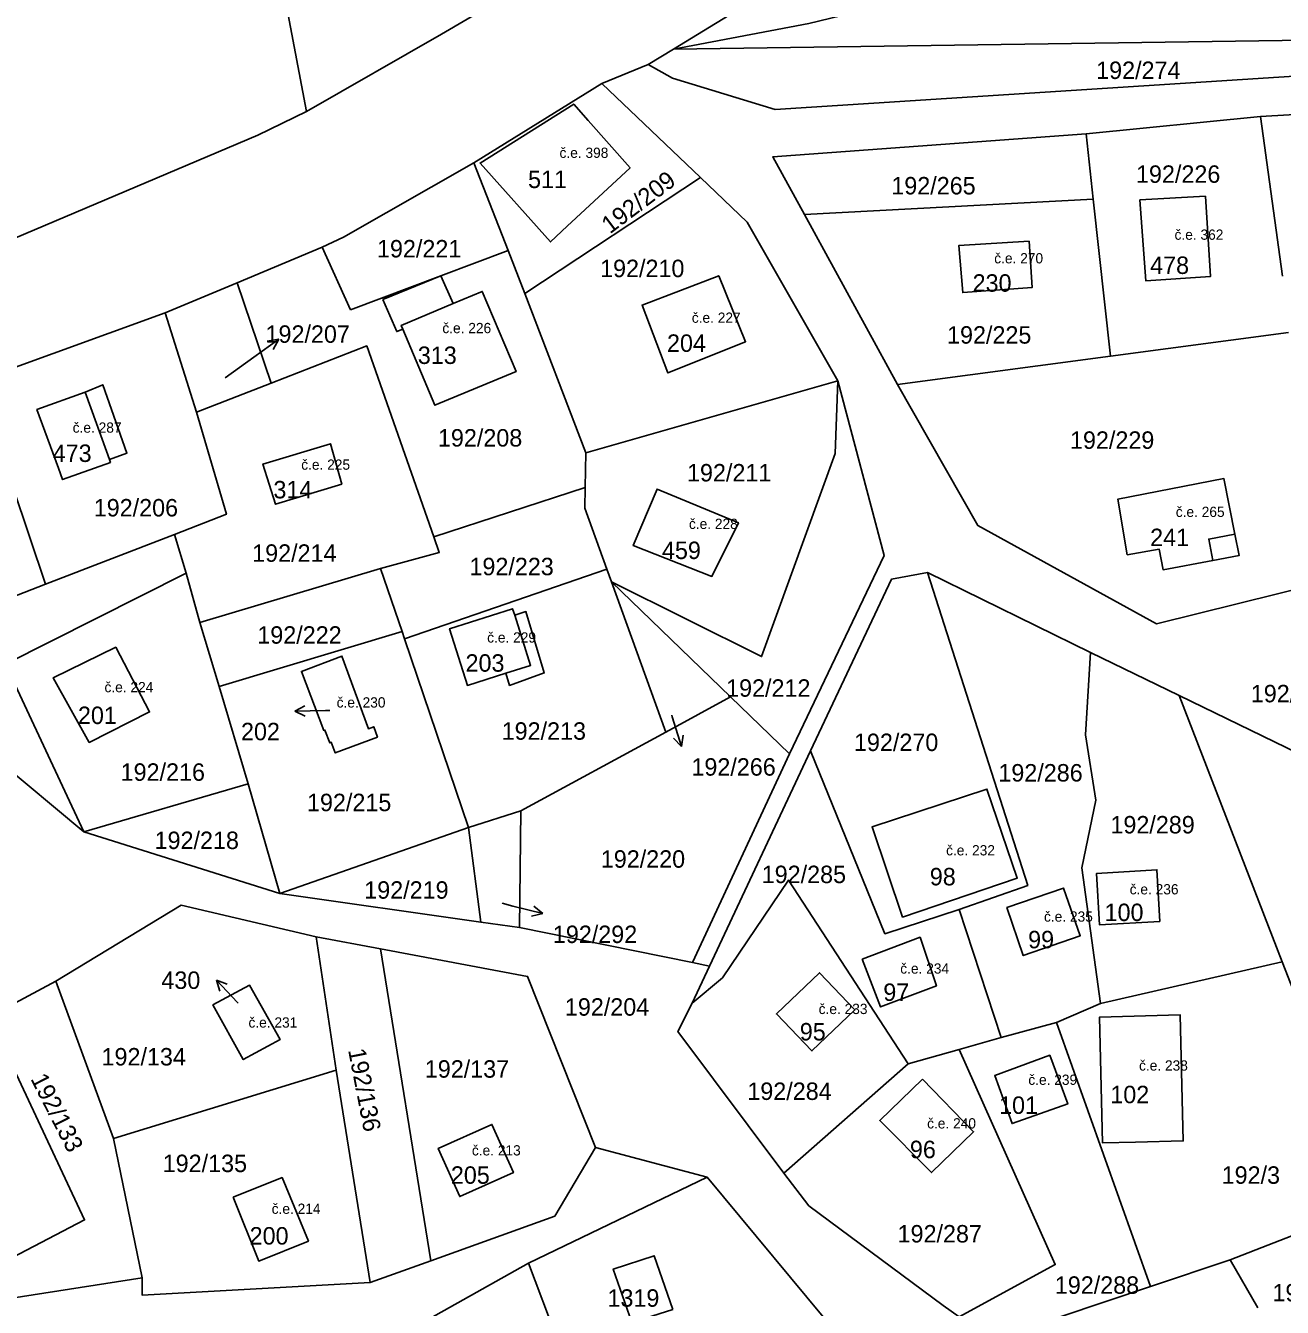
# Model space of a CAD drawing. Extents: x -887272 to -877616, y -1026687 to -1019819.
# Drawn here: x -882201.9 to -882079.4, y -1024136.8 to -1024011.9 of the extents above; entities that cross this region are included whole.
import ezdxf

# ---------------------------------------------------------------- set-up
doc = ezdxf.new("R2010")
doc.units = 0
for name, color, linetype in [('Definiční body', 7, 'Continuous'), ('Hranice parcel', 7, 'Continuous'), ('Parcelní čísla', 7, 'Continuous'), ('Polygon budovy', 7, 'Continuous'), ('Pop  PČ popisy', 7, 'Continuous'), ('Vnitřní kresba', 7, 'Continuous')]:
    doc.layers.add(name, color=color, linetype=linetype)

msp = doc.modelspace()

# ---------------------------------------------------------------- linework, layer by layer
at = {"layer": 'Hranice parcel'}
for p, q in [((-882138.72, -1024014.17), (-882123.98, -1024005.14)), ((-882141.19, -1024015.69), (-882138.72, -1024014.17)), ((-882145.71, -1024017.54), (-882141.19, -1024015.69)), ((-882145.71, -1024017.54), (-882158.18, -1024025.27)), ((-882136.1, -1024026.69), (-882145.71, -1024017.54)), ((-882081.54, -1024020.75), (-882098.51, -1024022.43)), ((-882079.39, -1024036.31), (-882081.54, -1024020.75)), ((-882098.51, -1024022.43), (-882097.82, -1024028.81)), ((-882158.18, -1024025.27), (-882154.84, -1024033.81)), ((-882153.2, -1024037.99), (-882136.1, -1024026.69)), ((-882097.82, -1024028.81), (-882125.97, -1024030.31)), ((-882096.15, -1024044.11), (-882097.82, -1024028.81)), ((-882125.97, -1024030.31), (-882116.91, -1024046.86)), ((-882172.96, -1024033.47), (-882181.25, -1024036.95)), ((-882170.21, -1024039.58), (-882172.96, -1024033.47)), ((-882153.2, -1024037.99), (-882154.84, -1024033.81)), ((-882181.25, -1024036.95), (-882188.26, -1024039.89)), ((-882177.94, -1024046.73), (-882181.25, -1024036.95)), ((-882147.26, -1024053.51), (-882153.2, -1024037.99)), ((-882206.58, -1024046.52), (-882188.26, -1024039.89)), ((-882188.26, -1024039.89), (-882185.22, -1024049.56)), ((-882096.15, -1024044.11), (-882078.8, -1024041.81)), ((-882116.91, -1024046.86), (-882096.15, -1024044.11)), ((-882199.93, -1024066.33), (-882206.58, -1024046.52)), ((-882185.22, -1024049.56), (-882177.94, -1024046.73)), ((-882147.26, -1024053.51), (-882122.72, -1024046.51)), ((-882147.32, -1024056.9), (-882147.26, -1024053.51)), ((-882162.09, -1024061.72), (-882147.32, -1024056.9)), ((-882187.35, -1024061.47), (-882199.93, -1024066.33)), ((-882186.22, -1024065.24), (-882187.35, -1024061.47)), ((-882167.27, -1024064.79), (-882184.87, -1024070.04)), ((-882165.18, -1024070.94), (-882167.27, -1024064.79)), ((-882145.21, -1024064.85), (-882164.94, -1024071.65)), ((-882145.21, -1024064.85), (-882144.76, -1024066.09)), ((-882199.93, -1024066.33), (-882217.07, -1024073.03)), ((-882184.87, -1024070.04), (-882186.22, -1024065.24)), ((-882144.76, -1024066.09), (-882133.16, -1024077.29)), ((-882139.48, -1024080.73), (-882144.76, -1024066.09)), ((-882098.08, -1024072.99), (-882113.98, -1024065.19)), ((-882183, -1024076.28), (-882184.87, -1024070.04)), ((-882165.18, -1024070.94), (-882183, -1024076.28)), ((-882164.94, -1024071.65), (-882165.18, -1024070.94)), ((-882164.94, -1024071.65), (-882158.69, -1024090.04)), ((-882196.2, -1024090.44), (-882217.07, -1024073.03)), ((-882089.45, -1024077.18), (-882098.08, -1024072.99)), ((-882183, -1024076.28), (-882180.16, -1024085.79)), ((-882133.16, -1024077.29), (-882139.48, -1024080.73)), ((-882133.16, -1024077.29), (-882127.41, -1024082.85)), ((-882089.45, -1024077.18), (-882079.4, -1024103.11)), ((-882153.6, -1024088.41), (-882139.48, -1024080.73)), ((-882125.39, -1024082.57), (-882135.22, -1024103.54)), ((-882136.89, -1024103.2), (-882127.41, -1024082.85)), ((-882196.2, -1024090.44), (-882180.16, -1024085.79)), ((-882180.16, -1024085.79), (-882177.1, -1024096.46)), ((-882158.69, -1024090.04), (-882153.6, -1024088.41)), ((-882153.6, -1024088.41), (-882153.74, -1024099.78)), ((-882177.1, -1024096.46), (-882158.69, -1024090.04)), ((-882157.5, -1024099.25), (-882158.69, -1024090.04)), ((-882177.1, -1024096.46), (-882196.2, -1024090.44)), ((-882157.5, -1024099.25), (-882177.1, -1024096.46)), ((-882106.8, -1024110.48), (-882110.89, -1024098.01)), ((-882153.74, -1024099.78), (-882157.5, -1024099.25)), ((-882136.89, -1024103.2), (-882153.74, -1024099.78)), ((-882171.6, -1024113.68), (-882173.55, -1024100.7)), ((-882167.27, -1024101.87), (-882173.55, -1024100.7)), ((-882162.36, -1024132.25), (-882167.27, -1024101.87)), ((-882136.92, -1024107.16), (-882135.22, -1024103.54)), ((-882135.22, -1024103.54), (-882136.89, -1024103.2)), ((-882079.4, -1024103.11), (-882097.11, -1024107.19)), ((-882076.7, -1024110.12), (-882079.4, -1024103.11)), ((-882205.42, -1024108.48), (-882198.92, -1024105.01)), ((-882198.92, -1024105.01), (-882193.28, -1024120.35)), ((-882097.11, -1024107.19), (-882101.42, -1024109.04)), ((-882106.8, -1024110.48), (-882101.42, -1024109.04)), ((-882101.42, -1024109.04), (-882092.24, -1024134.77)), ((-882110.9, -1024111.66), (-882106.8, -1024110.48)), ((-882115.87, -1024113.05), (-882110.9, -1024111.66)), ((-882193.28, -1024120.35), (-882171.6, -1024113.68)), ((-882168.3, -1024134.38), (-882171.6, -1024113.68)), ((-882127.99, -1024123.73), (-882115.87, -1024113.05)), ((-882114.47, -1024114.55), (-882118.63, -1024118.59)), ((-882193.28, -1024120.35), (-882190.49, -1024133.91)), ((-882135.46, -1024124.1), (-882146.33, -1024121.21)), ((-882125.54, -1024126.91), (-882127.99, -1024123.73)), ((-882152.85, -1024132.47), (-882135.46, -1024124.1)), ((-882121.99, -1024140.29), (-882135.46, -1024124.1)), ((-882084.49, -1024132.15), (-882072.69, -1024127.57)), ((-882168.3, -1024134.38), (-882162.36, -1024132.25)), ((-882147.02, -1024148.04), (-882152.85, -1024132.47)), ((-882092.24, -1024134.77), (-882084.49, -1024132.15)), ((-882084.49, -1024132.15), (-882081.79, -1024136.83)), ((-882190.49, -1024133.91), (-882208.64, -1024136.73)), ((-882092.24, -1024134.77), (-882105.5, -1024139.21))]:
    msp.add_line(p, q, dxfattribs=at)
for points in [[(-882174.49, -1024020.26), (-882208.33, -1023841.98), (-882227.5, -1023772.45), (-882213.17, -1023769.2), (-882180.99, -1023853.37), (-882162.93, -1023941.67)], [(-882138.72, -1024014.17), (-882125.55, -1024011.67), (-882085.96, -1024002.08), (-882063.17, -1024001.87), (-882034.49, -1024011.62), (-882004.55, -1024020.66), (-881996.26, -1024020.9)], [(-882148.29, -1024005.05), (-882161.34, -1024012.72), (-882174.49, -1024020.26)], [(-881966.06, -1024029.4), (-882045.19, -1024012.84), (-882138.72, -1024014.17)], [(-881990.45, -1024031.46), (-882004.32, -1024026.5), (-882043.3, -1024015.89), (-882047.34, -1024014.83), (-882128.82, -1024020.06), (-882138.81, -1024017.01), (-882141.19, -1024015.69)], [(-882147.04, -1024021.13), (-882148.45, -1024019.53), (-882157.57, -1024025.28), (-882150.72, -1024032.97)], [(-882057.94, -1024032.5), (-882065.31, -1024019.82), (-882081.54, -1024020.75)], [(-882340.1, -1024040.68), (-882291.8, -1024041.02), (-882266.44, -1024041.52), (-882231.92, -1024039.84), (-882208.92, -1024035.12), (-882179.22, -1024022.58), (-882174.49, -1024020.26)], [(-882150.72, -1024032.97), (-882149.08, -1024031.43), (-882142.96, -1024025.76), (-882147.04, -1024021.13)], [(-882098.51, -1024022.43), (-882129.05, -1024024.69), (-882125.97, -1024030.31)], [(-882158.18, -1024025.27), (-882170.87, -1024032.49), (-882172.96, -1024033.47)], [(-882122.72, -1024046.51), (-882131.54, -1024031.03), (-882136.1, -1024026.69)], [(-882086.4, -1024036.35), (-882086.89, -1024028.52), (-882093.28, -1024028.88), (-882092.71, -1024036.76), (-882086.4, -1024036.35)], [(-882154.84, -1024033.81), (-882161.39, -1024036.27), (-882170.21, -1024039.58)], [(-882103.78, -1024037.42), (-882104.08, -1024032.9), (-882110.92, -1024033.31), (-882110.54, -1024037.9), (-882103.78, -1024037.42)], [(-882160.2, -1024038.98), (-882161.39, -1024036.27), (-882167.05, -1024038.59)], [(-882141.79, -1024039.12), (-882139.27, -1024045.73), (-882131.7, -1024042.7), (-882134.31, -1024036.26), (-882141.79, -1024039.12)], [(-882167.05, -1024038.59), (-882165.7, -1024041.71), (-882165.11, -1024041.46), (-882161.99, -1024048.88), (-882154.07, -1024045.61), (-882157.36, -1024037.79), (-882160.2, -1024038.98)], [(-882177.94, -1024046.73), (-882168.62, -1024043.1), (-882162.09, -1024061.72)], [(-882198.66, -1024055), (-882198.26, -1024056.13), (-882193.59, -1024054.46), (-882193.69, -1024054.18), (-882191.99, -1024053.54), (-882194.34, -1024046.88), (-882196.04, -1024047.62), (-882200.75, -1024049.31), (-882198.66, -1024055)], [(-882144.76, -1024066.09), (-882130.14, -1024073.37), (-882122.96, -1024053.6), (-882122.72, -1024046.51)], [(-882127.41, -1024082.85), (-882118.21, -1024063.51), (-882122.72, -1024046.51)], [(-882116.91, -1024046.86), (-882109.08, -1024060.61), (-882091.67, -1024070.17), (-882075.8, -1024066.27)], [(-882187.35, -1024061.47), (-882182.29, -1024059.51), (-882185.22, -1024049.56)], [(-882172.16, -1024052.64), (-882178.74, -1024054.62), (-882177.51, -1024058.53), (-882171.05, -1024056.59), (-882172.16, -1024052.64)], [(-882091.02, -1024064.92), (-882086.18, -1024064.01), (-882083.62, -1024063.53), (-882084.03, -1024061.44), (-882085.09, -1024056.03), (-882095.44, -1024058.05), (-882094.51, -1024063.45), (-882091.4, -1024062.91), (-882091.02, -1024064.92)], [(-882147.32, -1024056.9), (-882147.35, -1024058.92), (-882145.21, -1024064.85)], [(-882132.4, -1024060.34), (-882140.32, -1024057.06), (-882142.64, -1024062.56), (-882134.98, -1024065.56), (-882132.4, -1024060.34)], [(-882162.09, -1024061.72), (-882161.56, -1024063.23), (-882167.27, -1024064.79)], [(-882186.22, -1024065.24), (-882203.83, -1024074.1), (-882196.2, -1024090.44)], [(-882113.98, -1024065.19), (-882117.47, -1024065.82), (-882125.39, -1024082.57)], [(-882110.89, -1024098.01), (-882104.21, -1024095.67), (-882113.98, -1024065.19)], [(-882154.4, -1024068.72), (-882160.55, -1024070.67), (-882158.8, -1024076.18), (-882155.08, -1024075), (-882154.7, -1024076.19), (-882151.32, -1024074.97), (-882153.11, -1024068.99), (-882154.2, -1024069.34), (-882154.4, -1024068.72)], [(-882189.78, -1024078.76), (-882193.08, -1024072.46), (-882199.16, -1024075.44), (-882195.66, -1024081.74), (-882189.78, -1024078.76)], [(-882171.68, -1024082.77), (-882167.58, -1024081.22), (-882167.94, -1024080.21), (-882168.46, -1024080.4), (-882171.04, -1024073.33), (-882174.98, -1024074.82), (-882172.81, -1024080.57), (-882172.7, -1024080.53), (-882172.22, -1024081.79), (-882172.07, -1024081.73), (-882171.68, -1024082.77)], [(-882097.11, -1024107.19), (-882098.95, -1024093.95), (-882097.56, -1024087.36), (-882098.57, -1024080.99), (-882098.08, -1024072.99)], [(-882060.37, -1024098.33), (-882059.72, -1024094.32), (-882061.57, -1024090.71), (-882089.45, -1024077.18)], [(-882125.39, -1024082.57), (-882118.13, -1024100.39), (-882110.89, -1024098.01)], [(-882119.38, -1024089.98), (-882116.4, -1024098.76), (-882105.23, -1024094.97), (-882108.18, -1024086.28), (-882119.38, -1024089.98)], [(-882091.34, -1024099.18), (-882091.62, -1024094.14), (-882097.51, -1024094.52), (-882097.21, -1024099.52), (-882091.34, -1024099.18)], [(-882115.87, -1024113.05), (-882127.53, -1024095.15), (-882133.96, -1024104.67), (-882136.92, -1024107.16)], [(-882104.64, -1024102.51), (-882099.09, -1024100.58), (-882100.71, -1024095.94), (-882106.24, -1024097.84), (-882104.64, -1024102.51)], [(-882173.55, -1024100.7), (-882186.69, -1024097.6), (-882198.92, -1024105.01)], [(-882120.33, -1024102.86), (-882118.57, -1024107.51), (-882113.1, -1024105.46), (-882114.69, -1024100.73), (-882120.33, -1024102.86)], [(-882146.33, -1024121.21), (-882152.94, -1024104.55), (-882167.27, -1024101.87)], [(-882124.49, -1024104.19), (-882128.69, -1024108.19), (-882125.24, -1024111.81), (-882121.04, -1024107.8), (-882124.49, -1024104.19)], [(-882183.61, -1024107.32), (-882180.65, -1024112.65), (-882177.07, -1024110.69), (-882180.05, -1024105.39), (-882183.61, -1024107.32)], [(-882127.99, -1024123.73), (-882138.29, -1024109.91), (-882136.92, -1024107.16)], [(-882205.42, -1024108.48), (-882196.11, -1024128.27), (-882209.58, -1024135.28)], [(-882096.91, -1024120.77), (-882093.7, -1024120.7), (-882089.06, -1024120.58), (-882089.12, -1024117.91), (-882089.36, -1024108.28), (-882097.2, -1024108.5), (-882096.91, -1024120.77)], [(-882110.9, -1024137.72), (-882101.52, -1024132.63), (-882110.9, -1024111.66)], [(-882102.06, -1024112.22), (-882107.42, -1024114.2), (-882105.74, -1024118.88), (-882100.3, -1024116.96), (-882102.06, -1024112.22)], [(-882118.63, -1024118.59), (-882113.58, -1024123.66), (-882109.48, -1024119.68), (-882114.47, -1024114.55)], [(-882154.32, -1024123.65), (-882156.42, -1024118.97), (-882161.65, -1024121.31), (-882159.55, -1024125.99), (-882154.32, -1024123.65)], [(-882162.36, -1024132.25), (-882150.29, -1024127.92), (-882146.33, -1024121.21)], [(-882181.64, -1024126.04), (-882179.14, -1024132.28), (-882174.3, -1024130.34), (-882176.86, -1024124.14), (-882181.64, -1024126.04)], [(-882110.9, -1024137.72), (-882112.46, -1024136.61), (-882125.54, -1024126.91)], [(-882167.7, -1024149.48), (-882166.92, -1024140.37), (-882152.85, -1024132.47)], [(-882138.78, -1024137), (-882142.8, -1024138.26), (-882144.6, -1024133.06), (-882140.6, -1024131.76), (-882138.78, -1024137)], [(-882190.49, -1024133.91), (-882190.51, -1024135.59), (-882168.3, -1024134.38)]]:
    msp.add_lwpolyline(points, dxfattribs=at)
at = {"layer": 'Polygon budovy'}
for points in [[(-882147.04, -1024021.13), (-882148.45, -1024019.53), (-882157.57, -1024025.28), (-882150.72, -1024032.97), (-882149.08, -1024031.43), (-882142.96, -1024025.76)], [(-882093.28, -1024028.88), (-882092.71, -1024036.76), (-882086.4, -1024036.35), (-882086.89, -1024028.52)], [(-882104.08, -1024032.9), (-882110.92, -1024033.31), (-882110.54, -1024037.9), (-882103.78, -1024037.42)], [(-882139.27, -1024045.73), (-882131.7, -1024042.7), (-882134.31, -1024036.26), (-882141.79, -1024039.12)], [(-882157.36, -1024037.79), (-882160.2, -1024038.98), (-882165.26, -1024041.11), (-882165.11, -1024041.46), (-882161.99, -1024048.88), (-882154.07, -1024045.61)], [(-882196.04, -1024047.62), (-882200.75, -1024049.31), (-882198.66, -1024055), (-882198.26, -1024056.13), (-882193.59, -1024054.46), (-882193.69, -1024054.18), (-882193.98, -1024053.35)], [(-882178.74, -1024054.62), (-882177.51, -1024058.53), (-882171.05, -1024056.59), (-882172.16, -1024052.64)], [(-882084.03, -1024061.44), (-882085.09, -1024056.03), (-882095.44, -1024058.05), (-882094.51, -1024063.45), (-882091.4, -1024062.91), (-882091.02, -1024064.92), (-882086.18, -1024064.01), (-882086.57, -1024061.93)], [(-882140.32, -1024057.06), (-882142.64, -1024062.56), (-882134.98, -1024065.56), (-882132.4, -1024060.34)], [(-882158.8, -1024076.18), (-882155.08, -1024075), (-882152.65, -1024074.23), (-882154.2, -1024069.34), (-882154.4, -1024068.72), (-882160.55, -1024070.67)], [(-882193.08, -1024072.46), (-882199.16, -1024075.44), (-882195.66, -1024081.74), (-882189.78, -1024078.76)], [(-882171.04, -1024073.33), (-882174.98, -1024074.82), (-882172.81, -1024080.57), (-882172.7, -1024080.53), (-882172.22, -1024081.79), (-882172.07, -1024081.73), (-882171.68, -1024082.77), (-882167.58, -1024081.22), (-882167.94, -1024080.21), (-882168.46, -1024080.4)], [(-882116.4, -1024098.76), (-882105.23, -1024094.97), (-882108.18, -1024086.28), (-882119.38, -1024089.98)], [(-882091.62, -1024094.14), (-882097.51, -1024094.52), (-882097.21, -1024099.52), (-882091.34, -1024099.18)], [(-882106.24, -1024097.84), (-882104.64, -1024102.51), (-882099.09, -1024100.58), (-882100.71, -1024095.94)], [(-882120.33, -1024102.86), (-882118.57, -1024107.51), (-882113.1, -1024105.46), (-882114.69, -1024100.73)], [(-882128.69, -1024108.19), (-882125.24, -1024111.81), (-882121.04, -1024107.8), (-882124.49, -1024104.19)], [(-882180.05, -1024105.39), (-882183.61, -1024107.32), (-882180.65, -1024112.65), (-882177.07, -1024110.69)], [(-882097.2, -1024108.5), (-882096.91, -1024120.77), (-882093.7, -1024120.7), (-882089.06, -1024120.58), (-882089.12, -1024117.91), (-882089.36, -1024108.28)], [(-882107.42, -1024114.2), (-882105.74, -1024118.88), (-882100.3, -1024116.96), (-882102.06, -1024112.22)], [(-882114.47, -1024114.55), (-882118.63, -1024118.59), (-882113.58, -1024123.66), (-882109.48, -1024119.68)], [(-882161.65, -1024121.31), (-882159.55, -1024125.99), (-882154.32, -1024123.65), (-882156.42, -1024118.97)], [(-882181.64, -1024126.04), (-882179.14, -1024132.28), (-882174.3, -1024130.34), (-882176.86, -1024124.14)]]:
    msp.add_lwpolyline(points, close=True, dxfattribs=at)
at = {"layer": 'Pop  PČ popisy'}
for p, q in [((-882179.63, -1024044.21), (-882177.2, -1024042.45)), ((-882177.2, -1024042.45), (-882178.31, -1024042.63)), ((-882177.2, -1024042.45), (-882177.72, -1024043.44)), ((-882182.42, -1024046.22), (-882179.63, -1024044.21)), ((-882175.64, -1024078.69), (-882174.65, -1024078.17)), ((-882172.64, -1024078.64), (-882175.64, -1024078.69)), ((-882175.64, -1024078.69), (-882174.63, -1024079.18)), ((-882172.64, -1024078.64), (-882172.22, -1024078.64)), ((-882138.89, -1024079.08), (-882138.84, -1024079.26)), ((-882138.84, -1024079.26), (-882137.96, -1024082.13)), ((-882137.96, -1024082.13), (-882138.73, -1024081.32)), ((-882137.96, -1024082.13), (-882137.78, -1024081.03)), ((-882155.43, -1024097.42), (-882154.38, -1024097.69)), ((-882154.38, -1024097.69), (-882151.47, -1024098.42)), ((-882151.47, -1024098.42), (-882152.56, -1024098.66)), ((-882151.47, -1024098.42), (-882152.32, -1024097.69)), ((-882181.21, -1024107.09), (-882183.26, -1024104.9)), ((-882183.26, -1024104.9), (-882182.21, -1024105.29)), ((-882183.26, -1024104.9), (-882182.94, -1024105.97)), ((-882181.16, -1024107.14), (-882181.21, -1024107.09))]:
    msp.add_line(p, q, dxfattribs=at)
at = {"layer": 'Vnitřní kresba'}
for p, q in [((-882160.2, -1024038.98), (-882165.26, -1024041.11)), ((-882165.26, -1024041.11), (-882165.11, -1024041.46)), ((-882196.04, -1024047.62), (-882193.98, -1024053.35)), ((-882193.98, -1024053.35), (-882193.69, -1024054.18)), ((-882084.03, -1024061.44), (-882086.57, -1024061.93)), ((-882086.18, -1024064.01), (-882086.57, -1024061.93)), ((-882154.2, -1024069.34), (-882152.65, -1024074.23)), ((-882155.08, -1024075), (-882152.65, -1024074.23))]:
    msp.add_line(p, q, dxfattribs=at)

# ---------------------------------------------------------------- texts
at = {"layer": 'Definiční body'}
for s, p in [('č.e. 398', (-882149.83, -1024024.78)), ('č.e. 362', (-882089.9, -1024032.76)), ('č.e. 270', (-882107.47, -1024035.06)), ('č.e. 227', (-882136.94, -1024040.85)), ('č.e. 226', (-882161.25, -1024041.86)), ('č.e. 287', (-882197.27, -1024051.56)), ('č.e. 225', (-882175, -1024055.17)), ('č.e. 265', (-882089.78, -1024059.77)), ('č.e. 228', (-882137.22, -1024060.94)), ('č.e. 229', (-882156.88, -1024072.01)), ('č.e. 224', (-882194.17, -1024076.85)), ('č.e. 230', (-882171.55, -1024078.34)), ('č.e. 232', (-882112.16, -1024092.75)), ('č.e. 236', (-882094.27, -1024096.55)), ('č.e. 235', (-882102.62, -1024099.21)), ('č.e. 234', (-882116.63, -1024104.27)), ('č.e. 233', (-882124.58, -1024108.21)), ('č.e. 231', (-882180.14, -1024109.53)), ('č.e. 238', (-882093.36, -1024113.72)), ('č.e. 239', (-882104.15, -1024115.11)), ('č.e. 240', (-882114.01, -1024119.36)), ('č.e. 213', (-882158.37, -1024121.99)), ('č.e. 214', (-882177.88, -1024127.68))]:
    msp.add_text(s, height=1, dxfattribs=at).set_placement(p)
at = {"layer": 'Parcelní čísla'}
for s, p in [('192/274', (-882097.54, -1024017.09)), ('511', (-882152.9, -1024027.72)), ('192/226', (-882093.66, -1024027.21)), ('192/265', (-882117.5, -1024028.34)), ('192/221', (-882167.62, -1024034.48)), ('192/210', (-882145.88, -1024036.4)), ('478', (-882092.28, -1024036.09)), ('230', (-882109.58, -1024037.82)), ('192/207', (-882178.48, -1024042.8)), ('192/225', (-882112.07, -1024042.88)), ('204', (-882139.36, -1024043.68)), ('313', (-882163.64, -1024044.86)), ('192/208', (-882161.68, -1024052.91)), ('192/229', (-882100.09, -1024053.13)), ('473', (-882199.22, -1024054.41)), ('192/211', (-882137.41, -1024056.31)), ('314', (-882177.71, -1024057.96)), ('192/206', (-882195.22, -1024059.72)), ('241', (-882092.28, -1024062.61)), ('192/214', (-882179.78, -1024064.14)), ('459', (-882139.85, -1024063.87)), ('192/223', (-882158.61, -1024065.45)), ('192/222', (-882179.28, -1024072.12)), ('203', (-882158.99, -1024074.85)), ('192/212', (-882133.6, -1024077.29)), ('192/224', (-882082.47, -1024077.83)), ('201', (-882196.76, -1024079.95)), ('202', (-882180.87, -1024081.53)), ('192/213', (-882155.47, -1024081.48)), ('192/270', (-882121.14, -1024082.58)), ('192/216', (-882192.6, -1024085.48)), ('192/266', (-882136.98, -1024084.98)), ('192/286', (-882107.07, -1024085.55)), ('192/215', (-882174.44, -1024088.44)), ('192/289', (-882096.15, -1024090.61)), ('192/218', (-882189.29, -1024092.13)), ('192/220', (-882145.81, -1024093.95)), ('192/285', (-882130.13, -1024095.45)), ('98', (-882113.75, -1024095.67)), ('192/219', (-882168.86, -1024096.97)), ('100', (-882096.72, -1024099.15)), ('192/292', (-882150.48, -1024101.29)), ('99', (-882104.17, -1024101.8)), ('430', (-882188.63, -1024105.76)), ('97', (-882118.28, -1024106.93)), ('192/204', (-882149.31, -1024108.37)), ('95', (-882126.42, -1024110.78)), ('192/134', (-882194.46, -1024113.22)), ('192/137', (-882162.96, -1024114.41)), ('192/284', (-882131.53, -1024116.58)), ('101', (-882107, -1024117.94)), ('102', (-882096.16, -1024116.9)), ('96', (-882115.69, -1024122.25)), ('192/135', (-882188.5, -1024123.61)), ('205', (-882160.42, -1024124.75)), ('192/3', (-882085.31, -1024124.75)), ('192/287', (-882116.89, -1024130.47)), ('200', (-882180.03, -1024130.67)), ('192/288', (-882101.57, -1024135.47)), ('1319', (-882145.16, -1024136.73)), ('192/258', (-882080.36, -1024136.21))]:
    msp.add_text(s, height=1.7, dxfattribs=at).set_placement(p)
for s, rotation, p in [('192/209', 37, (-882144.92, -1024032.24)), ('192/136', 281, (-882170.44, -1024111.72)), ('192/133', 297, (-882201.41, -1024114.52))]:
    msp.add_text(s, height=1.7, rotation=rotation, dxfattribs=at).set_placement(p)

doc.saveas('drawing.dxf')
